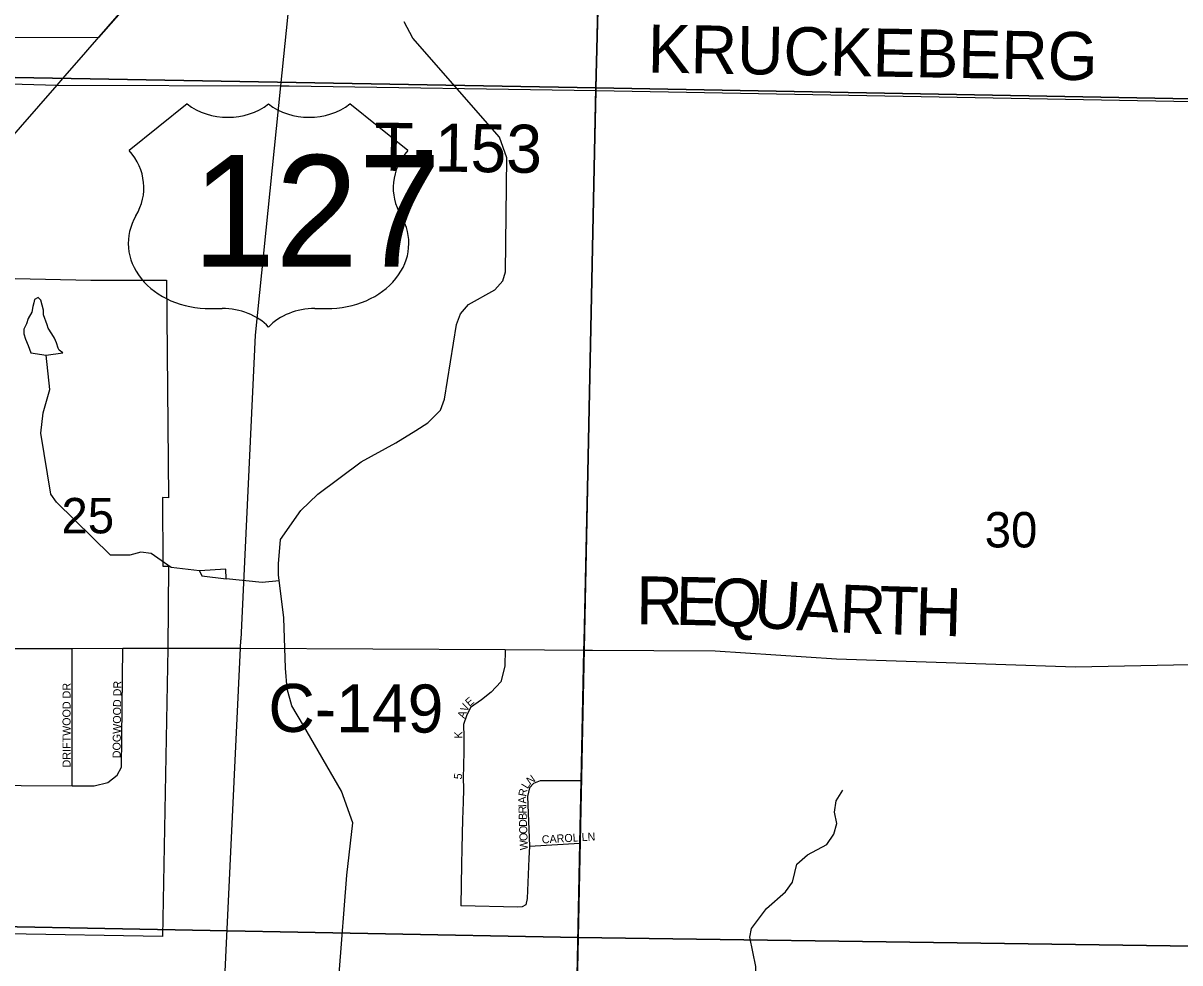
# Model space of a CAD drawing. Extents: x 0 to 1391, y -24 to 440.
# Drawn here: x 106.53 to 133.89, y 367.06 to 389.28 of the extents above; entities that cross this region are included whole.
import ezdxf

# ---------------------------------------------------------------- set-up
doc = ezdxf.new("R2010")
doc.units = 0
for name, color, linetype in [('GM_X_City_Street', 7, 'Continuous'), ('GM_X_City_Street_Text', 7, 'Continuous'), ('GM_X_Corporation', 7, 'Continuous'), ('GM_X_County_Road', 7, 'Continuous'), ('GM_X_County_Road_Text', 7, 'Continuous'), ('GM_X_Minor_Lake', 7, 'Continuous'), ('GM_X_Minor_River', 7, 'Continuous'), ('GM_X_Section', 7, 'Continuous'), ('GM_X_Section_Text', 7, 'Continuous'), ('GM_X_State_Route', 7, 'Continuous'), ('GM_X_Township_Road', 7, 'Continuous'), ('GM_X_Township_Road_Text', 7, 'Continuous'), ('GM_X_Township_Subdivision', 7, 'Continuous'), ('GM_X_Township_Subdivision_Text', 7, 'Continuous'), ('GM_X_US_Location', 7, 'Continuous'), ('GM_X_US_Route', 7, 'Continuous'), ('GM_X_US_Shield', 7, 'Continuous')]:
    doc.layers.add(name, color=color, linetype=linetype)

msp = doc.modelspace()

# ---------------------------------------------------------------- linework, layer by layer
at = {"layer": 'GM_X_City_Street'}
for points in [[(105.337, 371.269), (106.488, 371.261), (107.698, 371.253), (108.216, 371.25), (108.538, 371.33), (108.758, 371.505), (108.863, 371.692), (108.896, 374.501)], [(107.267, 374.499), (107.267, 374.499), (107.693, 374.499), (108.896, 374.501), (109.874, 374.503), (109.874, 374.503)], [(107.698, 371.253), (107.693, 374.499)], [(105.463, 374.496), (106.521, 374.498), (107.267, 374.499)]]:
    msp.add_lwpolyline(points, dxfattribs=at)
at = {"layer": 'GM_X_Corporation'}
for points in [[(106.328, 395.833), (107.617, 396.084), (110.982, 393.362), (110.044, 392.116), (109.739, 391.628), (109.465, 391.314), (108.034, 389.546), (108.847, 389.542), (108.318, 388.937), (106.234, 388.936)], [(105.624, 383.258), (108.139, 383.202), (109.923, 383.206), (109.972, 378.061), (109.828, 378.062), (109.835, 376.445), (109.969, 376.443), (109.96, 374.5), (109.829, 367.688), (106.148, 367.752)]]:
    msp.add_lwpolyline(points, dxfattribs=at)
at = {"layer": 'GM_X_County_Road'}
for points in [[(119.996, 374.457), (122.901, 374.439), (125.771, 374.251), (131.419, 374.061), (139.93, 374.235), (144.334, 374.282), (147.812, 374.287), (149.343, 374.454), (155.345, 375.705), (156.996, 376.105), (158.957, 376.654), (160.487, 377.208)], [(109.874, 374.503), (111.678, 374.506)], [(111.678, 374.506), (117.934, 374.469), (119.796, 374.459)], [(119.796, 374.459), (119.996, 374.457)]]:
    msp.add_lwpolyline(points, dxfattribs=at)
at = {"layer": 'GM_X_Minor_Lake'}
for points in [[(107.385, 381.55), (107.363, 381.594), (107.32, 381.722), (107.278, 381.829), (107.213, 381.936), (107.127, 382.065), (107.106, 382.15), (107.02, 382.385), (107.02, 382.493), (106.956, 382.728), (106.892, 382.792), (106.806, 382.749), (106.784, 382.664), (106.763, 382.578), (106.742, 382.45), (106.656, 382.3), (106.613, 382.171), (106.549, 382.043), (106.549, 381.936), (106.592, 381.807), (106.656, 381.657), (106.72, 381.486), (107.076, 381.434)], [(107.076, 381.434), (107.47, 381.487), (107.385, 381.55)], [(111.336, 376.142), (111.332, 376.37), (110.707, 376.335)], [(110.707, 376.335), (110.758, 376.213), (111.336, 376.142)]]:
    msp.add_lwpolyline(points, dxfattribs=at)
at = {"layer": 'GM_X_Minor_River'}
for points in [[(115.823, 379.653), (116.102, 379.829), (116.405, 380.127), (116.501, 380.392), (116.785, 382.156), (116.881, 382.405), (117.068, 382.629), (117.691, 382.975), (117.878, 383.184), (117.943, 383.403), (117.97, 386.092), (117.804, 386.588), (115.754, 388.927), (115.548, 389.311)], [(110.707, 376.335), (110.039, 376.408), (109.565, 376.744), (109.315, 376.771), (109.062, 376.7), (108.598, 376.701), (107.327, 377.955), (107.193, 378.147), (106.954, 379.587), (107.008, 380.064), (107.163, 380.616), (107.076, 381.434)], [(114.007, 366.803), (114.188, 369.141), (114.33, 370.377), (114.067, 371.125), (113.169, 372.679), (112.888, 373.138), (112.78, 373.545), (112.737, 374.034), (112.697, 375.22), (112.571, 376.24), (112.576, 376.499), (112.625, 377.075), (113.103, 377.759), (113.505, 378.148), (114.53, 378.912), (115.345, 379.355), (115.823, 379.653)], [(112.589, 376.095), (112.187, 376.058), (111.336, 376.142)], [(122.407, 362.404), (122.651, 362.541), (122.897, 362.822), (123.088, 363.272), (123.125, 363.697), (123.057, 364.354), (123.18, 364.617), (123.607, 365.051), (123.816, 365.576), (123.865, 366.975), (123.722, 367.673), (123.759, 367.878), (124.111, 368.352), (124.566, 368.74), (124.727, 368.97), (124.788, 369.204), (124.833, 369.401), (125.085, 369.62), (125.543, 369.863), (125.704, 370.108), (125.781, 370.357), (125.722, 370.626), (125.762, 370.898), (125.923, 371.151)]]:
    msp.add_lwpolyline(points, dxfattribs=at)
at = {"layer": 'GM_X_Section'}
for points in [[(100.608, 408.268), (120.596, 407.894), (120.081, 387.754), (100.138, 388.105)], [(140.682, 407.534), (140.129, 387.379), (120.081, 387.754), (120.596, 407.894)], [(100.138, 388.105), (120.081, 387.754), (119.659, 367.662), (99.755, 368.042)], [(120.081, 387.754), (140.129, 387.379), (139.822, 367.382), (119.659, 367.662)], [(99.755, 368.042), (119.659, 367.662), (119.229, 347.252), (99.204, 347.93)], [(119.659, 367.662), (139.822, 367.382), (139.614, 346.725), (134.652, 346.763), (119.229, 347.252)]]:
    msp.add_lwpolyline(points, close=True, dxfattribs=at)
at = {"layer": 'GM_X_State_Route'}
for points in [[(108.019, 388.594), (108.067, 388.65), (108.971, 389.685)], [(107.474, 387.97), (107.528, 388.032), (108.019, 388.594)], [(104.788, 384.895), (107.338, 387.814), (107.474, 387.97)]]:
    msp.add_lwpolyline(points, dxfattribs=at)
at = {"layer": 'GM_X_Township_Road'}
for points in [[(119.801, 374.659), (120.086, 387.691), (120.353, 402.009)], [(105.406, 387.866), (107.338, 387.814)], [(107.338, 387.814), (112.631, 387.801), (112.827, 387.798)], [(112.827, 387.798), (120.086, 387.691)], [(120.086, 387.691), (140.147, 387.318), (160.623, 387.168)], [(119.796, 374.459), (119.801, 374.659)], [(119.372, 352.043), (119.421, 355.251), (119.501, 358.654), (119.507, 360.328), (119.538, 361.855), (119.631, 366.374), (119.703, 369.893), (119.733, 371.367), (119.796, 374.459)]]:
    msp.add_lwpolyline(points, dxfattribs=at)
at = {"layer": 'GM_X_Township_Subdivision'}
for points in [[(117.934, 374.469), (117.925, 374.081), (117.83, 373.705), (117.601, 373.461), (117.371, 373.282), (117.116, 373.103), (117.019, 372.903), (116.952, 372.698), (116.957, 372.407), (116.957, 372.078), (116.952, 371.716), (116.938, 371.444), (116.947, 371.172), (116.938, 370.86), (116.928, 370.457), (116.909, 369.765), (116.904, 369.393), (116.895, 368.907), (116.885, 368.416)], [(119.733, 371.367), (118.761, 371.371), (118.602, 371.306), (118.507, 371.206), (118.464, 371.001), (118.508, 369.824), (118.497, 369.532), (118.454, 368.583), (118.426, 368.44), (118.335, 368.387), (118.235, 368.378), (116.885, 368.416)], [(118.508, 369.824), (119.703, 369.893)]]:
    msp.add_lwpolyline(points, dxfattribs=at)
at = {"layer": 'GM_X_US_Route'}
for points in [[(111.687, 374.701), (111.688, 374.705), (112.029, 381.903), (112.631, 387.801), (113.143, 392.811), (113.149, 392.93), (113.153, 393.015), (113.159, 393.125), (113.228, 394.484)], [(111.086, 362.045), (111.678, 374.506), (111.687, 374.701)]]:
    msp.add_lwpolyline(points, dxfattribs=at)
at = {"layer": 'GM_X_US_Shield'}
for p, q in [((110.415, 387.369), (109.042, 386.27)), ((115.634, 386.27), (114.261, 387.369)), ((110.965, 382.535), (111.239, 382.535)), ((113.437, 382.535), (113.711, 382.535))]:
    msp.add_line(p, q, dxfattribs=at)
for centre, major_axis, start_param, end_param in [((111.377, 388.153), (-1.373, 0), 0.795399, 2.346194), ((113.299, 388.153), (-1.373, 0), 0.795399, 2.346194), ((107.467, 385.388), (1.923, 0), 5.838949, 6.894067), ((117.209, 385.388), (-1.923, 0), 5.672304, 6.727422), ((110.943, 384.073), (1.923, 0), 2.702327, 4.723529), ((113.733, 384.073), (-1.923, 0), 1.559657, 3.580859), ((111.239, 381.436), (-1.373, 0), 3.785094, 4.712389), ((113.437, 381.436), (-1.373, 0), 4.712389, 5.639684)]:
    msp.add_ellipse(centre, major_axis=major_axis, ratio=0.8, start_param=start_param, end_param=end_param, dxfattribs=at)

# ---------------------------------------------------------------- texts
at = {"layer": 'GM_X_City_Street_Text'}
for s, height, rotation, p in [('DOGWOOD DR', 0.1894, 89.4035, (108.839, 371.901)), ('DRIFTWOOD DR', 0.18939, 90, (107.656, 371.684))]:
    msp.add_text(s, height=height, rotation=rotation, dxfattribs=at).set_placement(p)
at = {"layer": 'GM_X_County_Road_Text'}
for s, height, rotation, p in [('R', 1.136, 359.4536, (121.03, 375.067)), ('E', 1.136, 358.7442, (121.96, 375.058)), ('Q', 1.136, 357.3835, (122.802, 375.04)), ('U', 1.136, 356.3657, (123.796, 374.995)), ('A', 1.136, 356.8794, (124.805, 374.931)), ('R', 1.136, 357.8251, (125.824, 374.875)), ('T', 1.136, 358.3166, (126.767, 374.84)), ('H', 1.136, 358.3551, (127.618, 374.814)), ('C-149', 1.1364, 359.7247, (112.332, 372.526))]:
    msp.add_text(s, height=height, rotation=rotation, dxfattribs=at).set_placement(p)
at = {"layer": 'GM_X_Section_Text'}
for s, p in [('25', (107.441, 377.218)), ('30', (129.275, 376.885))]:
    msp.add_text(s, height=0.8371, rotation=0, dxfattribs=at).set_placement(p)
at = {"layer": 'GM_X_Township_Road_Text'}
for s, rotation, p in [('KRUCKEBERG', 358.9862, (121.299, 388.114)), ('T-153', 359.1569, (114.829, 385.795))]:
    msp.add_text(s, height=1.1364, rotation=rotation, dxfattribs=at).set_placement(p)
at = {"layer": 'GM_X_Township_Subdivision_Text'}
for s, height, rotation, p in [('V', 0.189, 64.0117, (117.029, 372.98)), ('E', 0.189, 40.9006, (117.09, 373.114)), ('A', 0.189, 69.9581, (116.974, 372.828)), ('K', 0.189, 90, (116.922, 372.367)), ('5', 0.189, 83.0362, (116.905, 371.394)), ('N', 0.189, 35.4424, (118.521, 371.264)), ('L', 0.189, 58.4493, (118.465, 371.165)), ('A', 0.189, 92.0056, (118.434, 370.831)), ('R', 0.189, 78.9984, (118.427, 370.987)), ('I', 0.189, 92.0002, (118.437, 370.748)), ('R', 0.189, 92.0038, (118.442, 370.598)), ('B', 0.189, 92.0099, (118.447, 370.448)), ('D', 0.189, 92.0002, (118.453, 370.282)), ('O', 0.189, 92.0056, (118.459, 370.115)), ('O', 0.189, 92.0056, (118.465, 369.948)), ('CAROL LN', 0.1894, 3.3191, (118.806, 369.886)), ('W', 0.189, 92.0052, (118.472, 369.732))]:
    msp.add_text(s, height=height, rotation=rotation, dxfattribs=at).set_placement(p)
at = {"layer": 'GM_X_US_Location'}
for s in ['0', '/']:
    msp.add_text(s, height=0.00379, dxfattribs=at).set_placement((112.34, 384.84))
msp.add_text('127', height=0.00379, rotation=0, dxfattribs=at).set_placement((111.175, 384.056))
at = {"layer": 'GM_X_US_Shield'}
msp.add_text('127', height=2.6367, dxfattribs=at).set_placement((110.537, 383.523))

doc.saveas('drawing.dxf')
